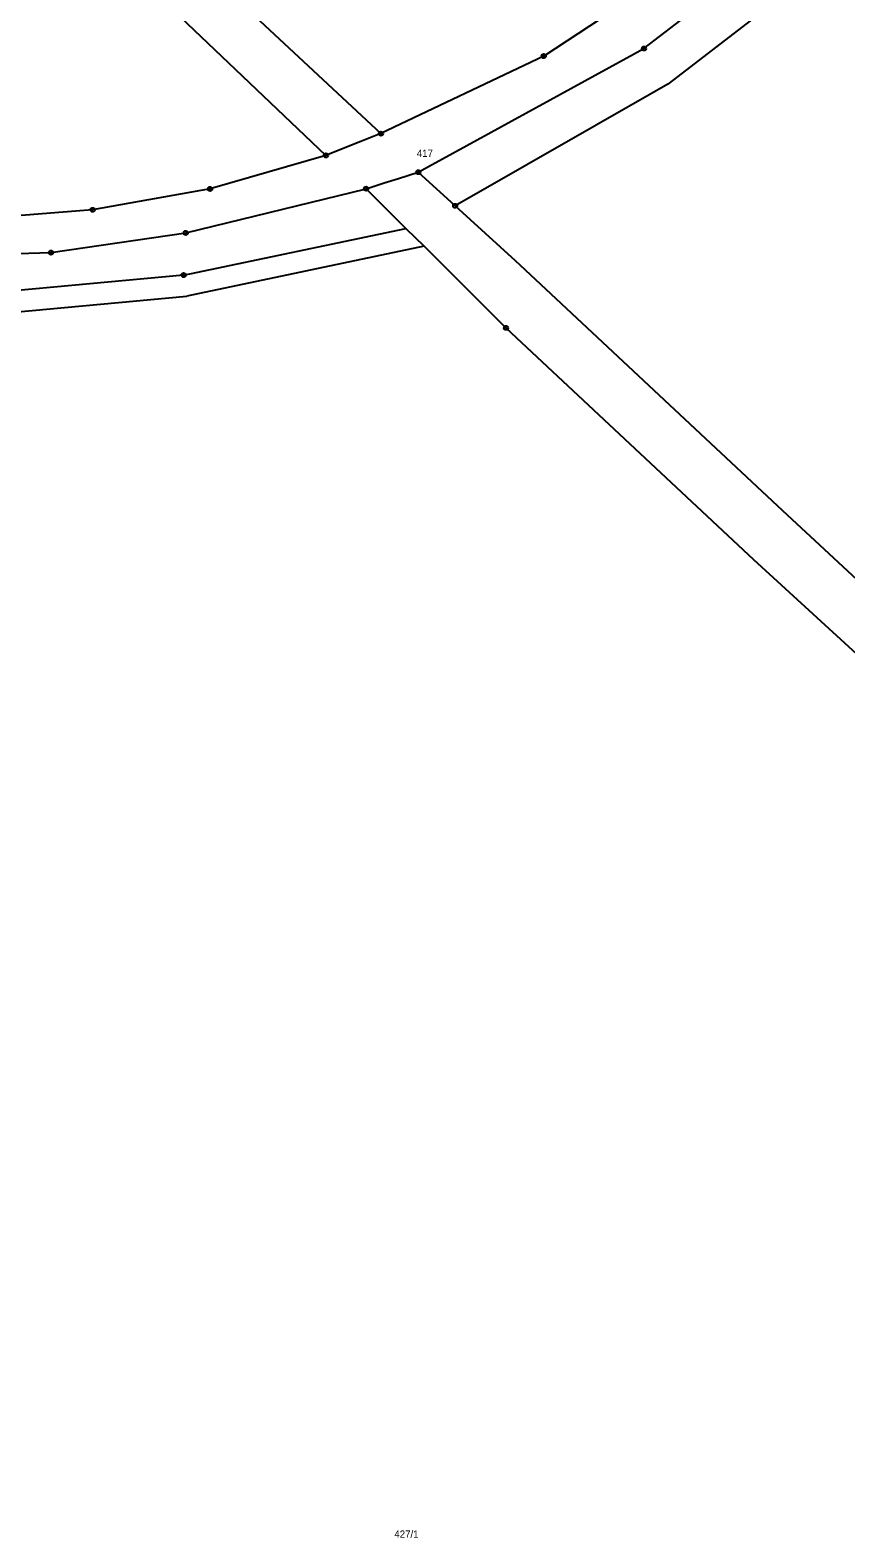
# Model space of a CAD drawing. Extents: x -759947 to -757003, y -1019641 to -1017100.
# Drawn here: x -759373.4 to -759182, y -1018152.4 to -1017798.6 of the extents above; entities that cross this region are included whole.
import ezdxf
from ezdxf.enums import TextEntityAlignment as Align

# ---------------------------------------------------------------- set-up
doc = ezdxf.new("R2010")
doc.units = 0
doc.header["$LTSCALE"] = 0.68
doc.layers.add('1', color=7, linetype='Continuous', lineweight=25)
doc.layers.add('8', color=7, linetype='Continuous', lineweight=25)
doc.layers.add('2', color=7, linetype='Continuous')

msp = doc.modelspace()

# ---------------------------------------------------------------- linework, layer by layer
at = {"layer": '1'}
for p, q in [((-759229.39, -1017802.88), (-759194.69, -1017776.1)), ((-759188.03, -1017783.59), (-759223.82, -1017811.22)), ((-759224.27, -1017785.83), (-759252.89, -1017804.65)), ((-759304, -1017827.96), (-759341.41, -1017792.38)), ((-759321.8, -1017794.26), (-759291.1, -1017822.86)), ((-759282.33, -1017831.9), (-759229.39, -1017802.88)), ((-759252.89, -1017804.65), (-759291.1, -1017822.86)), ((-759223.82, -1017811.22), (-759273.69, -1017839.79)), ((-759291.1, -1017822.86), (-759295.81, -1017824.72)), ((-759299.59, -1017826.22), (-759304, -1017827.96)), ((-759295.81, -1017824.72), (-759299.59, -1017826.22)), ((-759304, -1017827.96), (-759331.18, -1017835.83)), ((-759294.57, -1017835.77), (-759290.32, -1017834.43)), ((-759290.32, -1017834.43), (-759287.01, -1017833.38)), ((-759287.01, -1017833.38), (-759282.33, -1017831.9)), ((-759273.69, -1017839.79), (-759282.33, -1017831.9)), ((-759331.18, -1017835.83), (-759358.75, -1017840.73)), ((-759336.87, -1017846.16), (-759294.57, -1017835.77)), ((-759358.75, -1017840.73), (-759394.48, -1017843.55)), ((-759273.69, -1017839.79), (-759259.61, -1017852.64)), ((-759337.41, -1017856.04), (-759285.24, -1017845.12)), ((-759368.51, -1017850.77), (-759336.87, -1017846.16)), ((-759411.75, -1017851.95), (-759368.51, -1017850.77)), ((-759280.98, -1017849.26), (-759336.65, -1017860.99)), ((-759280.98, -1017849.26), (-759261.76, -1017868.43)), ((-759337.41, -1017856.04), (-759416.7, -1017863.43)), ((-759196.78, -1017911.39), (-759259.61, -1017852.64)), ((-759416.94, -1017868.47), (-759336.65, -1017860.99)), ((-759261.76, -1017868.43), (-759203.69, -1017922.8)), ((-759108.44, -1017993.65), (-759196.78, -1017911.39)), ((-759203.69, -1017922.8), (-759144.78, -1017976.85))]:
    msp.add_line(p, q, dxfattribs=at)
msp.add_lwpolyline([(-759294.57, -1017835.77), (-759285.24, -1017845.12), (-759280.98, -1017849.26)], dxfattribs=at)
at = {"layer": '8'}
for centre, radius in [((-759229.39, -1017802.8799), 0.5), ((-759229.39, -1017802.8799), 0.0303), ((-759252.89, -1017804.6499), 0.5), ((-759252.89, -1017804.6499), 0.0303), ((-759291.1, -1017822.8599), 0.5), ((-759291.1, -1017822.8599), 0.0303), ((-759304, -1017827.9599), 0.5), ((-759304, -1017827.9599), 0.0303), ((-759282.33, -1017831.8999), 0.5), ((-759282.33, -1017831.8999), 0.0303), ((-759331.18, -1017835.8299), 0.5), ((-759331.18, -1017835.8299), 0.0303), ((-759294.57, -1017835.7699), 0.5), ((-759294.57, -1017835.7699), 0.0303), ((-759358.75, -1017840.7299), 0.5), ((-759358.75, -1017840.7299), 0.0303), ((-759273.69, -1017839.7899), 0.5), ((-759273.69, -1017839.7899), 0.0303), ((-759336.87, -1017846.1599), 0.5), ((-759336.87, -1017846.1599), 0.0303), ((-759368.51, -1017850.7699), 0.5), ((-759368.51, -1017850.7699), 0.0303), ((-759337.41, -1017856.0399), 0.5), ((-759337.41, -1017856.0399), 0.0303), ((-759261.76, -1017868.4299), 0.5), ((-759261.76, -1017868.4299), 0.0303)]:
    msp.add_circle(centre, radius, dxfattribs=at)

# ---------------------------------------------------------------- texts
at = {"layer": '2'}
msp.add_text('417', height=1.7, dxfattribs=at).set_placement((-759282.68, -1017828.315))
msp.add_text('427/1', height=1.7, dxfattribs=at).set_placement((-759285.11, -1018152.355), align=Align.CENTER)

doc.saveas('drawing.dxf')
